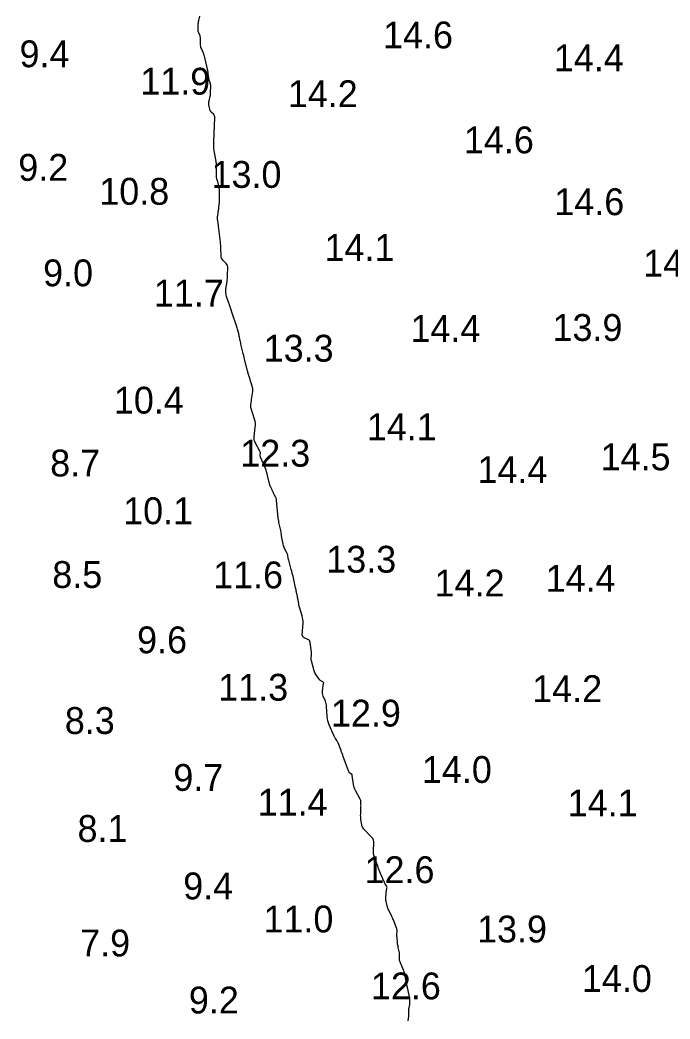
# Model space of a CAD drawing. Extents: x 815352 to 820877, y 582403 to 597439.
# Drawn here: x 820438.3 to 820559.4, y 590813 to 590999.1 of the extents above; entities that cross this region are included whole.
import ezdxf

# ---------------------------------------------------------------- set-up
doc = ezdxf.new("R2010")
doc.units = 0
doc.layers.add('V-CONT-EL12', color=7, linetype='Continuous')
doc.layers.add('V-TOPO-SOUN', color=7, linetype='Continuous')

msp = doc.modelspace()

# ---------------------------------------------------------------- linework, layer by layer
at = {"layer": 'V-CONT-EL12'}
msp.add_lwpolyline([(820510.58, 590812.59), (820510.7, 590813.48), (820510.72, 590813.62), (820510.73, 590813.77), (820510.74, 590813.91), (820510.74, 590814.05), (820510.75, 590814.7), (820510.76, 590814.8), (820510.76, 590814.9), (820510.78, 590815), (820510.8, 590815.09), (820510.88, 590815.48), (820510.9, 590815.57), (820510.91, 590815.67), (820510.92, 590815.77), (820510.93, 590815.87), (820510.94, 590816.53), (820510.94, 590816.67), (820510.93, 590816.81), (820510.91, 590816.95), (820510.88, 590817.09), (820510.72, 590817.73), (820510.69, 590817.87), (820510.66, 590818.01), (820510.62, 590818.15), (820510.59, 590818.29), (820510.47, 590818.85), (820510.44, 590818.99), (820510.41, 590819.14), (820510.38, 590819.28), (820510.35, 590819.42), (820509.99, 590821.22), (820509.92, 590821.51), (820509.84, 590821.79), (820509.75, 590822.07), (820509.64, 590822.35), (820509.06, 590823.76), (820509.01, 590823.88), (820508.99, 590824.01), (820508.97, 590824.13), (820508.98, 590824.26), (820509.01, 590824.78), (820509.02, 590824.91), (820509.01, 590825.04), (820509, 590825.17), (820508.98, 590825.3), (820508.76, 590826.29), (820508.72, 590826.5), (820508.68, 590826.71), (820508.65, 590826.92), (820508.63, 590827.13), (820508.53, 590828.17), (820508.52, 590828.31), (820508.51, 590828.44), (820508.51, 590828.58), (820508.52, 590828.71), (820508.55, 590829.26), (820508.55, 590829.39), (820508.54, 590829.52), (820508.51, 590829.65), (820508.47, 590829.78), (820507.86, 590831.42), (820507.77, 590831.63), (820507.69, 590831.83), (820507.59, 590832.03), (820507.49, 590832.23), (820507.07, 590833.04), (820506.98, 590833.23), (820506.89, 590833.42), (820506.82, 590833.61), (820506.76, 590833.81), (820506.55, 590834.62), (820506.5, 590834.82), (820506.47, 590835.03), (820506.46, 590835.23), (820506.46, 590835.44), (820506.52, 590836.49), (820506.53, 590836.6), (820506.54, 590836.71), (820506.56, 590836.82), (820506.58, 590836.92), (820506.66, 590837.35), (820506.67, 590837.46), (820506.66, 590837.56), (820506.63, 590837.66), (820506.58, 590837.75), (820506.34, 590838.14), (820506.28, 590838.23), (820506.22, 590838.33), (820506.17, 590838.43), (820506.13, 590838.53), (820505.46, 590840.08), (820505.34, 590840.38), (820505.22, 590840.67), (820505.1, 590840.97), (820504.99, 590841.27), (820504.31, 590843.18), (820504.21, 590843.49), (820504.15, 590843.79), (820504.13, 590844.11), (820504.13, 590844.42), (820504.22, 590845.7), (820504.21, 590846.01), (820504.14, 590846.3), (820504.01, 590846.56), (820503.82, 590846.8), (820502.37, 590848.31), (820502.21, 590848.5), (820502.09, 590848.7), (820502.01, 590848.92), (820501.96, 590849.16), (820501.82, 590850.14), (820501.79, 590850.38), (820501.77, 590850.63), (820501.76, 590850.87), (820501.77, 590851.12), (820501.82, 590852.51), (820501.82, 590852.63), (820501.83, 590852.75), (820501.82, 590852.86), (820501.82, 590852.98), (820501.8, 590853.45), (820501.79, 590853.56), (820501.77, 590853.67), (820501.73, 590853.78), (820501.68, 590853.89), (820500.81, 590855.5), (820500.68, 590855.78), (820500.57, 590856.07), (820500.49, 590856.36), (820500.44, 590856.67), (820500.21, 590858.35), (820500.19, 590858.43), (820500.16, 590858.5), (820500.11, 590858.55), (820500.05, 590858.6), (820499.77, 590858.77), (820499.7, 590858.82), (820499.65, 590858.88), (820499.61, 590858.94), (820499.57, 590859.01), (820498.52, 590861.87), (820498.42, 590862.14), (820498.32, 590862.42), (820498.21, 590862.69), (820498.11, 590862.97), (820497.55, 590864.4), (820497.51, 590864.51), (820497.45, 590864.61), (820497.4, 590864.72), (820497.33, 590864.82), (820497.06, 590865.21), (820497, 590865.31), (820496.94, 590865.41), (820496.88, 590865.52), (820496.83, 590865.62), (820495.92, 590867.75), (820495.77, 590868.13), (820495.67, 590868.51), (820495.59, 590868.89), (820495.55, 590869.29), (820495.42, 590871.17), (820495.39, 590871.42), (820495.35, 590871.67), (820495.28, 590871.92), (820495.19, 590872.16), (820494.8, 590873.12), (820494.72, 590873.37), (820494.68, 590873.61), (820494.66, 590873.86), (820494.68, 590874.12), (820494.87, 590875.44), (820494.88, 590875.54), (820494.85, 590875.63), (820494.8, 590875.7), (820494.72, 590875.77), (820494.35, 590875.99), (820494.26, 590876.05), (820494.18, 590876.11), (820494.1, 590876.19), (820494.04, 590876.27), (820493.46, 590877.08), (820493.35, 590877.25), (820493.26, 590877.42), (820493.18, 590877.61), (820493.12, 590877.8), (820492.59, 590879.71), (820492.56, 590879.84), (820492.55, 590879.98), (820492.54, 590880.11), (820492.55, 590880.24), (820492.59, 590880.78), (820492.6, 590880.91), (820492.6, 590881.05), (820492.59, 590881.18), (820492.58, 590881.31), (820492.35, 590883.13), (820492.31, 590883.31), (820492.22, 590883.46), (820492.1, 590883.58), (820491.94, 590883.67), (820491.23, 590883.98), (820491.07, 590884.08), (820490.97, 590884.2), (820490.91, 590884.35), (820490.89, 590884.53), (820491.03, 590886.71), (820491.03, 590887.05), (820491.01, 590887.38), (820490.96, 590887.72), (820490.87, 590888.04), (820490.37, 590889.69), (820490.32, 590889.85), (820490.28, 590890.01), (820490.25, 590890.18), (820490.22, 590890.34), (820490.12, 590891), (820490.09, 590891.16), (820490.07, 590891.32), (820490.03, 590891.49), (820490, 590891.65), (820489.82, 590892.5), (820489.78, 590892.69), (820489.73, 590892.89), (820489.69, 590893.09), (820489.65, 590893.28), (820489.17, 590895.43), (820489.1, 590895.76), (820489.02, 590896.08), (820488.94, 590896.4), (820488.85, 590896.72), (820488.36, 590898.41), (820488.33, 590898.52), (820488.31, 590898.62), (820488.28, 590898.73), (820488.27, 590898.84), (820488.2, 590899.28), (820488.18, 590899.38), (820488.15, 590899.49), (820488.11, 590899.59), (820488.06, 590899.69), (820487.6, 590900.61), (820487.51, 590900.8), (820487.44, 590900.99), (820487.38, 590901.19), (820487.33, 590901.39), (820487.04, 590902.98), (820487.02, 590903.04), (820487.01, 590903.1), (820487.01, 590903.16), (820487, 590903.23), (820486.97, 590903.47), (820486.96, 590903.53), (820486.95, 590903.59), (820486.94, 590903.65), (820486.93, 590903.71), (820486.6, 590905.2), (820486.54, 590905.46), (820486.5, 590905.73), (820486.46, 590906), (820486.43, 590906.27), (820486.11, 590909.61), (820486.09, 590909.75), (820486.05, 590909.89), (820486.01, 590910.02), (820485.95, 590910.14), (820485.67, 590910.69), (820485.62, 590910.79), (820485.56, 590910.9), (820485.51, 590911), (820485.47, 590911.11), (820485.25, 590911.63), (820485.22, 590911.69), (820485.18, 590911.76), (820485.15, 590911.83), (820485.11, 590911.89), (820484.97, 590912.15), (820484.93, 590912.22), (820484.9, 590912.28), (820484.88, 590912.35), (820484.86, 590912.42), (820484.43, 590914.23), (820484.35, 590914.55), (820484.25, 590914.87), (820484.15, 590915.19), (820484.02, 590915.5), (820483.14, 590917.62), (820483.11, 590917.71), (820483.08, 590917.8), (820483.07, 590917.9), (820483.07, 590917.99), (820483.09, 590918.38), (820483.09, 590918.47), (820483.07, 590918.56), (820483.04, 590918.65), (820483, 590918.73), (820482.16, 590920.23), (820482.03, 590920.52), (820481.95, 590920.81), (820481.91, 590921.11), (820481.93, 590921.42), (820482.14, 590923.19), (820482.17, 590923.58), (820482.16, 590923.96), (820482.1, 590924.34), (820482, 590924.72), (820481.36, 590926.72), (820481.33, 590926.85), (820481.31, 590926.99), (820481.3, 590927.12), (820481.32, 590927.25), (820481.38, 590927.8), (820481.4, 590927.93), (820481.42, 590928.07), (820481.44, 590928.2), (820481.46, 590928.34), (820481.67, 590929.83), (820481.69, 590930.03), (820481.68, 590930.23), (820481.66, 590930.43), (820481.61, 590930.62), (820481.37, 590931.47), (820481.32, 590931.63), (820481.27, 590931.79), (820481.22, 590931.95), (820481.17, 590932.11), (820480.93, 590932.86), (820480.89, 590932.97), (820480.86, 590933.08), (820480.83, 590933.18), (820480.8, 590933.29), (820480.68, 590933.72), (820480.66, 590933.83), (820480.63, 590933.94), (820480.6, 590934.05), (820480.57, 590934.16), (820480.13, 590935.96), (820480.05, 590936.27), (820479.98, 590936.57), (820479.91, 590936.87), (820479.83, 590937.18), (820479.47, 590938.68), (820479.43, 590938.84), (820479.39, 590939), (820479.36, 590939.17), (820479.32, 590939.33), (820479.2, 590939.99), (820479.17, 590940.15), (820479.13, 590940.32), (820479.09, 590940.48), (820479.05, 590940.64), (820478.8, 590941.5), (820478.74, 590941.69), (820478.68, 590941.89), (820478.62, 590942.08), (820478.56, 590942.28), (820477.93, 590944.27), (820477.8, 590944.66), (820477.68, 590945.06), (820477.54, 590945.45), (820477.41, 590945.85), (820476.81, 590947.58), (820476.72, 590947.91), (820476.66, 590948.24), (820476.65, 590948.57), (820476.68, 590948.91), (820476.88, 590950.34), (820476.91, 590950.64), (820476.94, 590950.94), (820476.97, 590951.24), (820476.98, 590951.54), (820477.02, 590952.89), (820477.01, 590953.11), (820476.96, 590953.31), (820476.86, 590953.5), (820476.72, 590953.68), (820476.09, 590954.35), (820475.96, 590954.52), (820475.86, 590954.71), (820475.79, 590954.92), (820475.77, 590955.14), (820475.73, 590956.49), (820475.72, 590956.8), (820475.7, 590957.1), (820475.67, 590957.4), (820475.64, 590957.7), (820475.3, 590960.66), (820475.29, 590960.79), (820475.27, 590960.91), (820475.25, 590961.04), (820475.24, 590961.16), (820475.14, 590961.77), (820475.13, 590961.84), (820475.12, 590961.91), (820475.12, 590961.98), (820475.12, 590962.04), (820475.12, 590962.32), (820475.12, 590962.38), (820475.12, 590962.45), (820475.13, 590962.52), (820475.14, 590962.59), (820475.3, 590963.7), (820475.33, 590963.9), (820475.35, 590964.09), (820475.37, 590964.29), (820475.39, 590964.49), (820475.45, 590965.29), (820475.47, 590965.49), (820475.48, 590965.69), (820475.48, 590965.89), (820475.48, 590966.09), (820475.46, 590967.4), (820475.45, 590967.53), (820475.44, 590967.67), (820475.42, 590967.8), (820475.39, 590967.94), (820475.27, 590968.49), (820475.24, 590968.61), (820475.21, 590968.73), (820475.18, 590968.85), (820475.14, 590968.97), (820474.99, 590969.44), (820474.96, 590969.56), (820474.93, 590969.68), (820474.92, 590969.8), (820474.92, 590969.93), (820474.92, 590970.48), (820474.92, 590970.62), (820474.93, 590970.75), (820474.93, 590970.88), (820474.93, 590971.02), (820474.93, 590971.93), (820474.92, 590972.13), (820474.91, 590972.32), (820474.89, 590972.52), (820474.86, 590972.71), (820474.51, 590974.74), (820474.45, 590975.14), (820474.41, 590975.54), (820474.4, 590975.95), (820474.41, 590976.36), (820474.62, 590980.89), (820474.61, 590981.05), (820474.57, 590981.2), (820474.5, 590981.33), (820474.4, 590981.45), (820473.94, 590981.91), (820473.84, 590982.04), (820473.76, 590982.17), (820473.7, 590982.31), (820473.66, 590982.47), (820473.52, 590983.25), (820473.49, 590983.43), (820473.49, 590983.61), (820473.5, 590983.8), (820473.53, 590983.98), (820473.74, 590984.89), (820473.78, 590985.09), (820473.81, 590985.29), (820473.82, 590985.49), (820473.83, 590985.7), (820473.85, 590986.62), (820473.85, 590986.77), (820473.84, 590986.91), (820473.81, 590987.05), (820473.78, 590987.18), (820473.61, 590987.73), (820473.57, 590987.87), (820473.54, 590988.01), (820473.51, 590988.15), (820473.49, 590988.29), (820473.4, 590989.01), (820473.38, 590989.18), (820473.36, 590989.34), (820473.32, 590989.51), (820473.29, 590989.67), (820472.76, 590992.06), (820472.7, 590992.28), (820472.64, 590992.49), (820472.56, 590992.7), (820472.48, 590992.91), (820472.1, 590993.76), (820472.03, 590993.95), (820471.98, 590994.15), (820471.95, 590994.35), (820471.94, 590994.55), (820471.97, 590995.48), (820471.96, 590995.64), (820471.94, 590995.79), (820471.91, 590995.94), (820471.85, 590996.09), (820471.61, 590996.66), (820471.55, 590996.81), (820471.52, 590996.96), (820471.5, 590997.11), (820471.49, 590997.26), (820471.52, 590998.19), (820471.53, 590998.38), (820471.56, 590998.57), (820471.59, 590998.76), (820471.63, 590998.95), (820471.84, 590999.77)], dxfattribs=at)

# ---------------------------------------------------------------- texts
at = {"layer": 'V-TOPO-SOUN'}
for s, p in [('14.6 ', (820505.93, 590993.78)), ('9.4', (820438.25, 590990.27)), ('14.4 ', (820537.74, 590989.52)), ('11.9 ', (820460.74, 590985.16)), ('14.2 ', (820488.2, 590982.83)), ('14.6 ', (820520.99, 590974.23)), ('9.2', (820438.02, 590969.11)), ('13.0 ', (820474, 590967.8)), ('10.8 ', (820453.1, 590964.65)), ('14.6 ', (820537.82, 590962.71)), ('14.1 ', (820495.04, 590954.18)), ('9.0', (820442.64, 590949.46)), ('14.8 ', (820554.38, 590951.26)), ('11.7 ', (820463.27, 590945.69)), ('14.4 ', (820511.04, 590939.09)), ('13.9 ', (820537.48, 590939.29)), ('13.3 ', (820483.71, 590935.42)), ('10.4 ', (820455.82, 590925.74)), ('14.1 ', (820502.91, 590920.79)), ('12.3 ', (820479.35, 590915.86)), ('14.5 ', (820546.44, 590915.18)), ('8.7', (820443.96, 590914.03)), ('14.4 ', (820523.51, 590912.81)), ('10.1 ', (820457.54, 590905.14)), ('13.3 ', (820495.36, 590896.11)), ('8.5', (820444.35, 590893.26)), ('11.6 ', (820474.3, 590893.19)), ('14.4 ', (820536.2, 590892.54)), ('14.2 ', (820515.53, 590891.68)), ('9.6', (820460.14, 590881.09)), ('11.3 ', (820475.25, 590872.26)), ('14.2 ', (820533.71, 590872)), ('8.3', (820446.68, 590866.06)), ('12.9 ', (820496.24, 590867.44)), ('14.0 ', (820513.17, 590856.94)), ('9.7', (820466.89, 590855.46)), ('11.4 ', (820482.59, 590850.84)), ('14.1 ', (820540.31, 590850.71)), ('8.1', (820449.05, 590845.95)), ('12.6 ', (820502.49, 590838.27)), ('9.4', (820468.73, 590835.25)), ('11.0 ', (820483.67, 590829.09)), ('13.9 ', (820523.44, 590827.22)), ('7.9', (820449.54, 590824.62)), ('14.0 ', (820542.96, 590818)), ('12.6 ', (820503.67, 590816.62)), ('9.2', (820469.78, 590813.99))]:
    msp.add_text(s, height=5, dxfattribs=at).set_placement(p)

doc.saveas('drawing.dxf')
